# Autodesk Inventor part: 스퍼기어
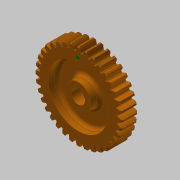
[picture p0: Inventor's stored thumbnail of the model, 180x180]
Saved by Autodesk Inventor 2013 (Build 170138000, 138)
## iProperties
Created: 2019-01
Part Number: 스퍼기어
Material: 알루미늄 6061
Document SubType Name: Modeling
Designer: mduedu
Density: 2.71 g/cm^3
Mass: 116.797 g
Surface Area: 167.013 cm^2
Volume: 43.0987 cm^3
Author: mduedu
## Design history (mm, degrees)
sketch "스케치1"
  geometry: C1 r 33.5 at (0, 0); C2 r 36 at (0, 0); C3 r 38 at (0, 0); 1 further point
  constraints: 3 centre point, 3 coincident
  dimensions: "d0" = 67 diameter of C1; "d2" = 72 diameter of C2; "d3" = 76 diameter of C3
extrude "돌출1" new body sketch "스케치1" distance "d4" = 14; taper "d5" = 0 deg
sketch "스케치2"
  geometry: L1 (0, 0)-(-38, 0); L2 (0, 0)-(0, 38); L3 (-0.57, 0)-(-0.57, 37.996); L4 (-1.57, 0)-(-1.57, 35.966); L5 (-2.07, 0)-(-2.07, 33.436); A1 r 38 centre (0, 0) between (-38, 0) and (0, 38) reference; A2 r 9.246 centre (7.162, 32.926) between (-0.57, 37.996) and (-2.07, 33.436); A3 r 9.246 centre (-7.162, 32.926) between (2.07, 33.436) and (0.57, 37.996); A4 r 33.5 centre (0, 0) between (2.07, 33.436) and (-2.07, 33.436); A5 r 38 centre (0, 0) between (0.57, 37.996) and (-0.57, 37.996); 2 further points
  constraints: 12 point on circle, 10 end point, 4 centre point, 3 parallel, 3 symmetric about line, 2 coincident, 1 horizontal, 1 perpendicular, 5 other
  dimensions: "d6" = 0.5 distance between parallel lines of L4 L5; "d8" = 1 distance between parallel lines of L3 L4; "d9" = 1.57 distance between parallel lines of L2 L4
extrude "돌출2" join sketch "스케치2" stored distance "d10" = 14; taper "d11" = 0 deg
chamfer "모따기1" distance "d12" = 1; stored, may be unused: second distance "d13" = 2, angle "d14" = 45 deg
fillet "모깎기1" dims "d15" = 0.5
sketch "스케치3"
  geometry: C1 r 11 at (0, 0); 1 further point
  constraints: 1 centre point, 1 coincident
  dimensions: "d19" = 22 diameter of C1
extrude "돌출3" join sketch "스케치3" distance "d20" = 7; taper "d21" = 0 deg
fillet "모깎기2" dims "d22" = 3
sketch "스케치4"
  geometry: C1 r 11 at (0, 0); C2 r 26 at (0, 0); 1 further point
  constraints: 2 centre point, 2 coincident
  dimensions: "d23" = 22 diameter of C1; "d24" = 52 diameter of C2
extrude "돌출4" cut sketch "스케치4" distance "d25" = 8; taper "d26" = 0 deg
fillet "모깎기3" dims "d27" = 3
sketch "스케치5" dims "d28" = 60
  geometry: C1 r 1.5 at (0, 30); 2 further points
  constraints: 2 vertical alignment, 1 centre point, 1 coincident, 2 other
  dimensions: "d29" = 3 diameter of C1
extrude "돌출5" join sketch "스케치5" distance "d30" = 0.5; taper "d31" = 0 deg
sketch "스케치6"
  geometry: L1 (-2, 5.657)-(2, 5.657); L2 (2, 5.657)-(2, 7.8); L3 (2, 7.8)-(-2, 7.8); L4 (-2, 7.8)-(-2, 5.657); A1 r 6 centre (0, 0) between (-2, 5.657) and (2, 5.657); 1 further point
  constraints: 8 end point, 2 parallel, 2 point on circle, 1 centre point, 1 coincident, 1 horizontal, 1 perpendicular
  dimensions: "d32" = 13.8 dimension on A1 L3; "d34" = 4 distance of L2.end L3.end; "d35" = 12 diameter of A1
extrude "돌출6" cut sketch "스케치6" stored distance "d36" = 0.5; taper "d37" = 0 deg
chamfer "모따기2" distance "d38" = 1; stored, may be unused: second distance "d39" = 2, angle "d40" = 45 deg
node "솔리드1"
pattern_circular "원형 패턴1" dims "d17" = 360 deg
